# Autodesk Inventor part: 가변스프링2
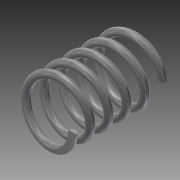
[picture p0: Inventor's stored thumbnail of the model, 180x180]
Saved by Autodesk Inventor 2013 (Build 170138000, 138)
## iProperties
Created: 2015-02
Part Number: 가변스프링2
Material: 강철, 탄소
Document SubType Name: Modeling
Designer: WINDOWS7
Mass: 18.8942 g
Surface Area: 32.5242 cm^2
Volume: 2.40079 cm^3
Density: 7.87 g/cm^3
Author: WINDOWS7
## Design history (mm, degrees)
sketch "스케치1"
  geometry: L1 (0, 0)-(11, 0); L2 (11, 0)-(11, 36.411); L3 (11, 36.411)-(0, 36.411); L4 (0, 36.411)-(0, 0); C1 r 1.5 at (11, 0)
  constraints: 8 end point, 2 parallel, 1 centre point, 1 coincident, 1 horizontal, 1 perpendicular
  dimensions: "d0" = 36.4112 distance of L3.end L1.start (derived); "d2" = 22 diameter of L2 L4; "d3" = 3 diameter of C1
feature "코일1" sketch "스케치1" pitch "d4" = 10; turns "d6" = 5; dims "d5" = 36.4112 (= d0), "d7" = 0, angle "d8" = 90 deg, angle "d9" = 90 deg, "d10" = 0, "d11" = 0
feature "분할1"
node "작업 평면1"
feature "분할2"
node "솔리드1"
other parameters: "d12" = 90 deg
